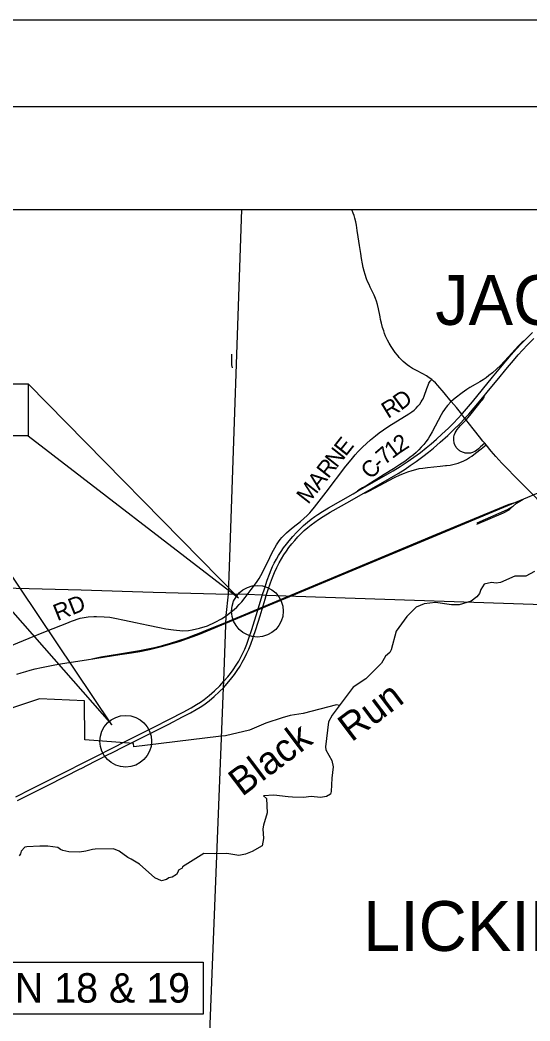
# Model space of a CAD drawing. Extents: x 0 to 34, y 0 to 22.
# Drawn here: x 14.77 to 17.72, y 16.22 to 22 of the extents above; entities that cross this region are included whole.
import ezdxf

# ---------------------------------------------------------------- set-up
doc = ezdxf.new("R2010")
doc.units = 0
for name, color, linetype in [('BR_P_Gen_Text', 7, 'Continuous'), ('Default', 7, 'Continuous'), ('GM_X_County', 7, 'Continuous'), ('GM_X_County_Road', 7, 'Continuous'), ('GM_X_County_Road_Text', 7, 'Continuous'), ('GM_X_Interchange_Ramps', 7, 'Continuous'), ('GM_X_Minor_River', 7, 'Continuous'), ('GM_X_Minor_River_Text', 7, 'Continuous'), ('GM_X_Rail_Line', 7, 'Continuous'), ('GM_X_State_Route', 7, 'Continuous'), ('GM_X_Township', 7, 'Continuous'), ('GM_X_Township_Text', 7, 'Continuous'), ('SH_Border', 7, 'Continuous'), ('SH_Cut_Line', 7, 'Continuous'), ('SH_Text', 7, 'Continuous')]:
    doc.layers.add(name, color=color, linetype=linetype)

msp = doc.modelspace()

# ---------------------------------------------------------------- linework, layer by layer
at = {"layer": 'BR_P_Gen_Text'}
for points in [[(12.6681, 19.8992), (14.8201, 19.8992), (14.8201, 19.5989), (12.6681, 19.5989)], [(14.8201, 19.8992), (14.8201, 19.5989), (16.0331, 18.6645)], [(14.4514, 19.1999), (14.4514, 18.8997), (15.3028, 17.9312)], [(13.6851, 16.5609), (15.8312, 16.5609), (15.8312, 16.2607), (13.6851, 16.2607)]]:
    msp.add_lwpolyline(points, close=True, dxfattribs=at)
at = {"layer": 'Default'}
for centre in [(16.1433, 18.5871), (15.3836, 17.8365)]:
    msp.add_circle(centre, 0.149, dxfattribs=at)
at = {"layer": 'GM_X_County'}
msp.add_lwpolyline([(15.7461, 13.067), (15.7838, 14.1047), (15.8705, 16.2037), (15.9482, 18.1471), (15.9491, 18.1833), (15.9623, 18.562), (15.9755, 18.686), (15.9829, 18.8439), (16.0536, 20.907)], dxfattribs=at)
at = {"layer": 'GM_X_County_Road'}
for points in [[(16.1922, 18.85), (16.2016, 18.8687), (16.2292, 18.9252), (16.2436, 18.953), (16.2541, 18.971), (16.2655, 18.9885), (16.2747, 19.0012), (16.2845, 19.0133), (16.295, 19.0248), (16.31, 19.0393), (16.3256, 19.0531), (16.3499, 19.073), (16.3909, 19.1056), (16.4109, 19.1225), (16.4303, 19.1403), (16.445, 19.1553), (16.4554, 19.1672), (16.472, 19.1875), (16.5393, 19.2745), (16.6541, 19.424), (16.6834, 19.4609), (16.707, 19.4889), (16.7246, 19.5082), (16.7502, 19.5343), (16.7728, 19.556), (16.7963, 19.5768), (16.8246, 19.6), (16.8454, 19.6159), (16.8709, 19.6341), (16.9013, 19.6545), (17.0165, 19.727), (17.0342, 19.7384), (17.0468, 19.748), (17.0586, 19.7586), (17.0694, 19.7701), (17.0794, 19.7824), (17.0884, 19.7954), (17.0938, 19.8045), (17.0985, 19.814), (17.1043, 19.8287), (17.1198, 19.8732), (17.1273, 19.8926), (17.1327, 19.9031), (17.1361, 19.9089), (17.1402, 19.9143), (17.1489, 19.924)], [(15.9639, 18.5616), (15.9818, 18.575), (16.0085, 18.5965), (16.0239, 18.6108), (16.0385, 18.6259), (16.0524, 18.6417), (16.0722, 18.6662), (16.0842, 18.6819), (16.1071, 18.7119), (16.1262, 18.7369), (16.1415, 18.7582), (16.1529, 18.7759), (16.1635, 18.794), (16.1805, 18.8265), (16.1922, 18.85)], [(14.5173, 18.3053), (14.8268, 18.432), (14.9204, 18.4697), (15.0092, 18.5044), (15.0438, 18.5184), (15.0699, 18.529), (15.1212, 18.547), (15.1662, 18.554), (15.1999, 18.5564), (15.2156, 18.5558), (15.2587, 18.5552), (15.2912, 18.553), (15.3198, 18.5474), (15.377, 18.5352), (15.4397, 18.5217), (15.5125, 18.5072), (15.5777, 18.4923), (15.6158, 18.4848), (15.6584, 18.4794), (15.7124, 18.4741), (15.745, 18.4758), (15.7674, 18.4799), (15.8089, 18.4893), (15.8554, 18.5031), (15.8988, 18.5232), (15.9368, 18.5434), (15.9626, 18.5611)]]:
    msp.add_lwpolyline(points, dxfattribs=at)
at = {"layer": 'GM_X_Interchange_Ramps'}
for points in [[(17.6814, 20.1472), (17.6712, 20.141), (17.6493, 20.1184), (17.5921, 20.0558), (17.5669, 20.0285), (17.5449, 20.0061), (17.5222, 19.9846), (17.4986, 19.9639), (17.4784, 19.9473), (17.4617, 19.9346), (17.4446, 19.9227), (17.4269, 19.9114), (17.3997, 19.8958), (17.368, 19.8776), (17.3502, 19.8666), (17.3371, 19.8579), (17.3244, 19.8487), (17.2835, 19.8162), (17.261, 19.7985)], [(17.4547, 19.5566), (17.4306, 19.5355), (17.4188, 19.5251), (17.4062, 19.5156), (17.3974, 19.5099), (17.388, 19.5052), (17.3832, 19.5033), (17.3782, 19.5017), (17.3731, 19.5004), (17.368, 19.4995), (17.3628, 19.4988), (17.3575, 19.4986), (17.3523, 19.4987), (17.3471, 19.4992), (17.3419, 19.5), (17.3368, 19.5011), (17.3317, 19.5026), (17.3268, 19.5043), (17.3219, 19.5064), (17.3172, 19.5087), (17.3127, 19.5114), (17.3084, 19.5143), (17.3042, 19.5175), (17.3003, 19.521), (17.2966, 19.5247), (17.2932, 19.5287), (17.29, 19.5329), (17.2872, 19.5373), (17.2846, 19.5419), (17.2823, 19.5466), (17.2786, 19.5564), (17.2773, 19.5615), (17.2756, 19.5718), (17.2752, 19.5771), (17.2755, 19.5875), (17.2762, 19.5927), (17.2785, 19.6029), (17.2801, 19.6079), (17.2843, 19.6174), (17.2894, 19.6266), (17.2953, 19.6352), (17.3051, 19.6476), (17.3155, 19.6594), (17.3408, 19.6861), (17.3466, 19.6927), (17.3581, 19.7058), (17.3757, 19.7273), (17.4342, 19.7992), (17.4407, 19.8076), (17.4476, 19.8179), (17.4504, 19.8236), (17.4525, 19.833)], [(17.261, 19.7985), (17.2397, 19.7742), (17.2323, 19.7653), (17.2268, 19.7579), (17.2217, 19.7512), (17.2133, 19.7381), (17.2032, 19.7198), (17.1693, 19.6549), (17.1518, 19.6228), (17.1386, 19.6003), (17.1272, 19.5827), (17.1152, 19.5657), (17.1023, 19.5492), (17.0886, 19.5334), (17.0741, 19.5183), (17.059, 19.5039), (17.0433, 19.4902), (17.0228, 19.4739), (16.9934, 19.4522), (16.9633, 19.4314), (16.9282, 19.4086), (16.8748, 19.3757), (16.7739, 19.313), (16.7493, 19.2996), (16.7299, 19.288), (16.7214, 19.2799)], [(17.2272, 19.4273), (17.2339, 19.4281), (17.2547, 19.4311), (17.2702, 19.4341), (17.2855, 19.4379), (17.3006, 19.4425), (17.3155, 19.4479), (17.33, 19.4541), (17.3488, 19.4634), (17.3671, 19.4739), (17.3802, 19.4826), (17.4011, 19.4986), (17.4339, 19.525), (17.462, 19.5476)], [(16.7539, 19.2669), (16.7668, 19.2698), (16.7851, 19.2801), (16.8517, 19.3155), (16.9011, 19.3418), (16.934, 19.3583), (16.9674, 19.3738), (16.9916, 19.384), (17.0113, 19.3916), (17.0363, 19.3998), (17.0566, 19.4053), (17.0771, 19.41), (17.0978, 19.4138), (17.1239, 19.4172), (17.1973, 19.4238), (17.2272, 19.4273)]]:
    msp.add_lwpolyline(points, dxfattribs=at)
at = {"layer": 'GM_X_Minor_River'}
for points in [[(16.0003, 19.9915), (15.9962, 20.0102), (15.9959, 20.0703)], [(17.7409, 18.8156), (17.6917, 18.7892), (17.6278, 18.789), (17.5448, 18.7536), (17.5205, 18.7484), (17.4942, 18.7534), (17.4508, 18.7436), (17.4311, 18.7129), (17.4235, 18.6892), (17.4082, 18.6693), (17.3769, 18.6442), (17.3067, 18.6241), (17.2632, 18.6233), (17.1698, 18.6371), (17.1059, 18.6305), (17.058, 18.6099), (17.0045, 18.5566), (16.9433, 18.4725), (16.9149, 18.3649), (16.9067, 18.3482), (16.8812, 18.327), (16.8589, 18.2872), (16.7684, 18.1973), (16.6963, 18.1491), (16.5747, 17.9874), (16.5525, 17.9483), (16.5357, 17.8042), (16.537, 17.7863), (16.573, 17.7256), (16.5802, 17.6878), (16.5727, 17.6238), (16.5691, 17.5469), (16.5641, 17.5303), (16.5411, 17.5168), (16.5066, 17.5122), (16.4535, 17.5171), (16.4088, 17.5119), (16.3448, 17.5142), (16.3212, 17.5148), (16.2374, 17.5254), (16.1792, 17.5207), (16.1959, 17.5054), (16.1987, 17.4235), (16.1791, 17.3524), (16.1747, 17.3306), (16.1774, 17.2749), (16.1706, 17.2333), (16.1138, 17.2004), (16.0735, 17.1837), (16.0365, 17.1771), (15.9904, 17.1853), (15.9674, 17.1891), (15.8933, 17.1873)], [(15.1463, 18.0691), (14.8866, 18.0813), (14.58, 17.9789)], [(15.9191, 17.8641), (15.4301, 17.8047), (15.4275, 17.8226), (15.1479, 17.8451), (15.1463, 18.0691)], [(16.617, 18.0436), (16.5995, 18.0457), (16.4072, 17.9958), (16.3318, 17.9853), (16.2851, 17.9717), (16.1912, 17.94), (16.0967, 17.9007), (15.9587, 17.8682), (15.9191, 17.8641)], [(15.8933, 17.1873), (15.8337, 17.1889), (15.7118, 17.1122), (15.7087, 17.1045), (15.6876, 17.0923), (15.6844, 17.0801), (15.6762, 17.0679), (15.6513, 17.0524), (15.6328, 17.0479), (15.6187, 17.0382), (15.5906, 17.0298), (15.5522, 17.0488), (15.4623, 17.1265), (15.4155, 17.1563), (15.395, 17.1658), (15.3462, 17.2027), (15.3123, 17.216), (15.2067, 17.2136), (15.192, 17.211), (15.1537, 17.2019), (15.1173, 17.1953), (15.0546, 17.197), (15.0213, 17.2058), (15.0066, 17.2108), (14.9912, 17.2223), (14.9348, 17.2303), (14.8888, 17.2314), (14.814, 17.2266), (14.8025, 17.2253), (14.7802, 17.2015), (14.7757, 17.1861), (14.7688, 17.1746)]]:
    msp.add_lwpolyline(points, dxfattribs=at)
at = {"layer": 'GM_X_Rail_Line'}
for points in [[(15.9608, 18.5184), (17.1741, 19.0245), (17.5653, 19.1881), (18.1909, 19.4493), (18.992, 19.7843), (19.068, 19.816)], [(15.9589, 18.5228), (17.1723, 19.029), (17.5634, 19.1925), (17.5944, 19.2055), (17.6302, 19.2152)], [(17.4093, 19.0901), (17.5617, 19.1546), (17.5948, 19.1721), (17.6148, 19.1911)], [(17.411, 19.0978), (17.5859, 19.175), (17.6148, 19.1911)], [(17.6148, 19.1911), (17.6181, 19.1942), (17.6376, 19.2116), (17.6765, 19.2345)], [(14.7556, 18.2241), (14.7808, 18.2321), (14.8064, 18.2397), (14.8317, 18.2463), (14.8617, 18.2538), (14.8977, 18.262), (14.9363, 18.2706), (14.9739, 18.2778), (15.0181, 18.2853), (15.1571, 18.3067), (15.3491, 18.3366), (15.417, 18.3472), (15.4645, 18.3553), (15.5215, 18.3668), (15.5509, 18.3733), (15.5969, 18.3849), (15.6431, 18.3978), (15.6919, 18.413), (15.7397, 18.4293), (15.7729, 18.4414), (15.8085, 18.4552), (15.8545, 18.4742), (15.9608, 18.5184)], [(15.1876, 18.3114), (15.2395, 18.3244), (15.3483, 18.3413), (15.4162, 18.3519), (15.4636, 18.3601), (15.5205, 18.3715), (15.5497, 18.378), (15.5957, 18.3895), (15.6417, 18.4024), (15.6904, 18.4175), (15.7381, 18.4338), (15.7712, 18.4459), (15.8067, 18.4597), (15.8527, 18.4786), (15.9589, 18.5228)]]:
    msp.add_lwpolyline(points, dxfattribs=at)
at = {"layer": 'GM_X_State_Route'}
msp.add_line((15.2263, 17.7304), (15.2867, 17.7609), dxfattribs=at)
for points in [[(16.9522, 20.0629), (16.951, 20.0643), (16.9379, 20.0808), (16.9255, 20.0975), (16.9146, 20.1148), (16.903, 20.1347), (16.894, 20.1519), (16.8829, 20.1757), (16.8769, 20.1902), (16.8715, 20.2049), (16.8651, 20.2248), (16.8583, 20.2501), (16.8537, 20.2705), (16.8507, 20.286), (16.8486, 20.2961), (16.8415, 20.332), (16.8354, 20.3572), (16.8298, 20.3772), (16.8245, 20.3919), (16.8166, 20.4111), (16.8078, 20.4299), (16.794, 20.458), (16.7873, 20.4722), (16.7788, 20.4913), (16.773, 20.5059), (16.7644, 20.5306), (16.7584, 20.5507), (16.7536, 20.5711), (16.7494, 20.5916), (16.7438, 20.6224), (16.7388, 20.6515), (16.7318, 20.6974), (16.7245, 20.7479), (16.7188, 20.7841), (16.7139, 20.8151), (16.7102, 20.8357), (16.7054, 20.8559), (16.7012, 20.871), (16.6961, 20.8857), (16.6905, 20.9002), (16.6874, 20.907)], [(15.9495, 18.1824), (15.9722, 18.2075), (15.9884, 18.2282), (16.0039, 18.2494), (16.0215, 18.2755), (16.0352, 18.2979), (16.048, 18.3208), (16.0598, 18.3443), (16.0705, 18.3682), (16.0823, 18.3975), (16.0946, 18.4321), (16.1109, 18.4819), (16.1433, 18.5871), (16.1714, 18.6784), (16.185, 18.7223), (16.1998, 18.7671), (16.2124, 18.8015), (16.2223, 18.8257), (16.2309, 18.8448), (16.2401, 18.8636), (16.2524, 18.8866), (16.2656, 18.9092), (16.2796, 18.9313), (16.2944, 18.9528), (16.31, 18.9738), (16.3262, 18.9943), (16.3467, 19.0181), (16.3681, 19.041), (16.3903, 19.0633), (16.4093, 19.0812), (16.4329, 19.1019), (16.4532, 19.1184), (16.4741, 19.1341), (16.4913, 19.146), (16.5177, 19.163), (16.5537, 19.1845), (16.6949, 19.2649), (16.7214, 19.2799), (16.8864, 19.3735), (16.927, 19.3976), (16.967, 19.4226), (17.0064, 19.4487), (17.0451, 19.4758), (17.0831, 19.5038), (17.1163, 19.5295), (17.1446, 19.5529), (17.1763, 19.5804), (17.2074, 19.6086), (17.2455, 19.6447), (17.2715, 19.6705), (17.3006, 19.7007), (17.3218, 19.7238), (17.3255, 19.7278), (17.3498, 19.7553), (17.3837, 19.7954), (17.5, 19.9373), (17.5766, 20.0303), (17.6071, 20.0663), (17.6383, 20.1017), (17.6669, 20.1323), (17.6814, 20.1472), (17.6998, 20.1661), (17.7298, 20.1953)], [(17.3355, 19.6958), (17.3402, 19.7007), (17.3619, 19.7247), (17.3927, 19.7605), (17.4525, 19.833), (17.4761, 19.8616), (17.5266, 19.9218), (17.5866, 19.9946), (17.6198, 20.0352), (17.6469, 20.0672), (17.6715, 20.0946), (17.7005, 20.1249), (17.7377, 20.1618)], [(17.3525, 19.6851), (17.3466, 19.6927), (17.3402, 19.7007), (17.327, 19.7174), (17.3218, 19.7238), (17.2908, 19.7623), (17.261, 19.7985), (17.2212, 19.8468), (17.1838, 19.8907), (17.17, 19.905), (17.1593, 19.9152), (17.1489, 19.924), (17.1346, 19.9346), (17.1176, 19.9456), (17.0967, 19.9572), (17.061, 19.9762), (17.0379, 19.989), (17.0207, 19.9997), (17.0078, 20.0087), (16.9952, 20.0184), (16.9841, 20.0283), (16.9717, 20.0402), (16.9617, 20.0517), (16.9522, 20.0629)], [(16.3994, 19.0392), (16.4134, 19.0524), (16.4332, 19.0697), (16.4536, 19.0862), (16.4747, 19.1019), (16.4963, 19.1167), (16.5229, 19.1337), (16.5634, 19.1579), (16.677, 19.2233), (16.7539, 19.2669), (16.8275, 19.3086), (16.9048, 19.3529), (16.9545, 19.3822), (16.9945, 19.4071), (17.025, 19.4273), (17.0593, 19.4515), (17.0972, 19.4795), (17.1302, 19.5052), (17.1585, 19.5286), (17.1979, 19.563), (17.2406, 19.6017), (17.2748, 19.6342), (17.312, 19.6711), (17.3355, 19.6958)], [(17.6396, 19.3533), (17.6259, 19.3668), (17.6185, 19.3743), (17.5929, 19.4006), (17.5533, 19.4419), (17.5181, 19.4809), (17.4914, 19.5115), (17.462, 19.5476), (17.4547, 19.5566), (17.444, 19.5696), (17.4243, 19.594), (17.3952, 19.6312), (17.3595, 19.6763), (17.3525, 19.6851)], [(17.8242, 19.1666), (17.685, 19.3076), (17.6704, 19.3224), (17.6409, 19.352), (17.6396, 19.3533)], [(16.1185, 18.4349), (16.119, 18.4365), (16.1339, 18.4812), (16.1587, 18.5613), (16.1878, 18.6566), (16.1944, 18.6776), (16.205, 18.7117), (16.2185, 18.7514), (16.2294, 18.781), (16.2414, 18.8101), (16.2546, 18.8387), (16.2689, 18.8668), (16.2817, 18.8897), (16.2954, 18.9121), (16.31, 18.934), (16.3253, 18.9553), (16.3414, 18.976), (16.3582, 18.9962), (16.3759, 19.0156), (16.3943, 19.0344), (16.3994, 19.0392)], [(15.9486, 18.1462), (15.9955, 18.2015), (16.0112, 18.2224), (16.026, 18.244), (16.0428, 18.2705), (16.056, 18.2931), (16.0708, 18.3207), (16.0824, 18.3442), (16.093, 18.368), (16.1047, 18.3972), (16.1185, 18.4349)], [(14.9316, 17.6074), (14.9406, 17.6119), (15.0435, 17.6641), (15.1339, 17.7099), (15.2149, 17.7508), (15.3056, 17.7966), (15.3836, 17.8365), (15.4605, 17.8751), (15.545, 17.9178), (15.6353, 17.9637), (15.7155, 18.005), (15.7611, 18.0293), (15.7926, 18.0484), (15.8147, 18.0627), (15.8362, 18.0782), (15.8655, 18.1009), (15.896, 18.1273), (15.926, 18.1567), (15.9495, 18.1824)], [(15.4209, 17.8289), (15.4586, 17.848), (15.5402, 17.8894), (15.6315, 17.9357), (15.7119, 17.9767), (15.7564, 17.9998), (15.7904, 18.0194), (15.8137, 18.0337), (15.8336, 18.0471), (15.8644, 18.0698), (15.8943, 18.0945), (15.9232, 18.1207), (15.9486, 18.1462)], [(15.2867, 17.7609), (15.2988, 17.767), (15.3787, 17.8075), (15.4209, 17.8289)], [(15.1216, 17.6775), (15.1261, 17.6798), (15.2067, 17.7205), (15.2263, 17.7304)], [(14.9276, 17.5788), (14.9321, 17.5811), (15.0347, 17.6336), (15.1216, 17.6775)], [(14.7488, 17.515), (14.8404, 17.561), (14.9316, 17.6074)], [(14.7589, 17.4939), (14.8391, 17.5341), (14.9276, 17.5788)]]:
    msp.add_lwpolyline(points, dxfattribs=at)
at = {"layer": 'GM_X_Township'}
for points in [[(7.2878, 13.067), (7.3449, 14.3381), (7.3457, 14.3583), (7.3798, 15.3309), (7.3804, 15.3492), (7.3808, 15.3569), (7.3817, 15.3787), (7.3819, 15.3847), (7.4355, 16.6384), (7.5303, 18.6845), (7.5438, 18.9496), (8.5619, 18.9174), (10.8875, 18.8291), (12.1312, 18.787), (15.1269, 18.7101), (15.5418, 18.6967), (15.9755, 18.686)], [(19.068, 18.5614), (19.021, 18.563), (18.0755, 18.6144), (16.194, 18.6785), (16.1711, 18.6793), (16.0838, 18.6828), (15.9755, 18.686)]]:
    msp.add_lwpolyline(points, dxfattribs=at)
at = {"layer": 'SH_Border'}
msp.add_lwpolyline([(1.5, 21.5), (33.5, 21.5), (33.5, 0.5), (1.5, 0.5)], close=True, dxfattribs=at)
at = {"layer": 'SH_Cut_Line'}
msp.add_lwpolyline([(0, 0), (34, 0), (34, 22), (0, 22)], close=True, dxfattribs=at)
at = {"layer": 'SH_Text'}
msp.add_lwpolyline([(1.9289, 20.907), (19.068, 20.907), (19.068, 13.067), (1.9289, 13.067)], close=True, dxfattribs=at)

# ---------------------------------------------------------------- texts
at = {"layer": 'BR_P_Gen_Text'}
msp.add_text('LOCATION 18 & 19', height=0.17, dxfattribs=at).set_placement((13.7459, 16.3275))
at = {"layer": 'GM_X_County_Road_Text'}
for s, height, rotation, p in [('D', 0.0959, 36.8025, (16.9713, 19.743)), ('R', 0.0959, 31.47045, (16.8962, 19.6965)), ('E', 0.0959, 51.62999, (16.6523, 19.4768)), ('2', 0.0959, 33.16537, (16.9664, 19.4986)), ('N', 0.0959, 51.91479, (16.6004, 19.4105)), ('7', 0.0959, 40.96246, (16.8779, 19.4273)), ('1', 0.0959, 36.58955, (16.9206, 19.4645)), ('R', 0.0959, 51.91927, (16.5518, 19.3485)), ('C', 0.0959, 48.98276, (16.8014, 19.3434)), ('-', 0.0959, 44.77218, (16.8514, 19.401)), ('A', 0.0959, 51.91998, (16.4998, 19.2821)), ('M', 0.0959, 51.91907, (16.4356, 19.2002)), ('RD', 0.09588, 21.71314, (14.9892, 18.5293))]:
    msp.add_text(s, height=height, rotation=rotation, dxfattribs=at).set_placement(p)
at = {"layer": 'GM_X_Minor_River_Text'}
for s, p in [('Run', (16.6858, 17.8284)), ('Black', (16.0543, 17.5136))]:
    msp.add_text(s, height=0.1598, rotation=37.02688, dxfattribs=at).set_placement(p)
at = {"layer": 'GM_X_Township_Text'}
for s, p in [('JACKSON', (17.1688, 20.2398)), ('LICKING', (16.7525, 16.6259))]:
    msp.add_text(s, height=0.28764, rotation=0.00001, dxfattribs=at).set_placement(p)

doc.saveas('drawing.dxf')
